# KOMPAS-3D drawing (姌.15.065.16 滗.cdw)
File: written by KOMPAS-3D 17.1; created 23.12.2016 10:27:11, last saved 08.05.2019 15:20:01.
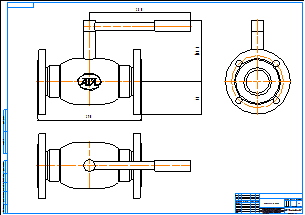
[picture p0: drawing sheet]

Sheet 1: A1, landscape

Title block, sheet 1: name: КШ.15.065.16 фф; material: Внимание! Данный продукт является объектом авторского права ООО «Торговый Дом АДЛ». / Запрещается изменение, копирование, распространение / (в том числе путем копирования на другие сайты и ресурсы в Интернете) / или любое иное использование информации и объектов без предварительного / согласия правообладателя (ООО «Торговый Дом АДЛ»).; sheets: 1; organisation: ООО "Торговый дом АДЛ"; sheet format: A1; stored path: C:\Users\tra\Desktop\2д чертежи\Шаровые краны БИВАЛ\КШ_Бивал_серия_14_15\KOMPAS_2D\КШ.15.065.16 фф.cdw

Views: Вид 1, Проекционный вид 2, Проекционный вид 3
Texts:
  Klimkovich
  ADL
Dimensions and other numbers on the sheet: 290; 280; 168,8; 90; 1:1; 1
